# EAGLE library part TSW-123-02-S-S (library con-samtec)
THROUGH-HOLE .025" SQ POST HEADER Source: Samtec TSW.pdf
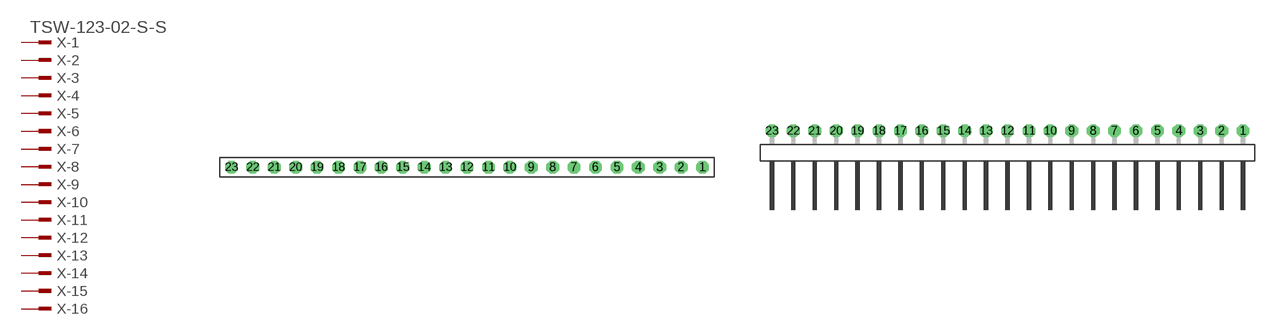
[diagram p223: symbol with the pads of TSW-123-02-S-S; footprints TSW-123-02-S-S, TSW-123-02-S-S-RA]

Designator prefix X; gates -1=MPINV -2=MPIN -3=MPIN -4=MPIN -5=MPIN -6=MPIN -7=MPIN -8=MPIN -9=MPIN -10=MPIN -11=MPIN -12=MPIN -13=MPIN -14=MPIN -15=MPIN -16=MPIN -17=MPIN -18=MPIN -19=MPIN -20=MPIN -21=MPIN -22=MPIN -23=MPIN

## TSW-123-02-S-S (OC_FARNELL: unknown; OC_NEWARK: unknown)  [TSW-123-02-S-S]
1  -1:1  pas
2  -2:1  pas
3  -3:1  pas
4  -4:1  pas
5  -5:1  pas
6  -6:1  pas
7  -7:1  pas
8  -8:1  pas
9  -9:1  pas
10  -10:1  pas
11  -11:1  pas
12  -12:1  pas
13  -13:1  pas
14  -14:1  pas
15  -15:1  pas
16  -16:1  pas
17  -17:1  pas
18  -18:1  pas
19  -19:1  pas
20  -20:1  pas
21  -21:1  pas
22  -22:1  pas
23  -23:1  pas

## TSW-123-02-S-S-RA (OC_FARNELL: unknown; OC_NEWARK: unknown)  [TSW-123-02-S-S-RA]
Pads as for TSW-123-02-S-S

## Footprint TSW-123-02-S-S (pad centres in mm)
THROUGH-HOLE .025" SQ POST HEADER Source: Samtec TSW.pdf
drill 1 pad 1.5 octagon: 1 27.94,0; 2 25.4,0; 3 22.86,0; 4 20.32,0; 5 17.78,0; 6 15.24,0; 7 12.7,0; 8 10.16,0; 9 7.62,0; 10 5.08,0; 11 2.54,0; 12 0,0; 13 -2.54,0; 14 -5.08,0; 15 -7.62,0; 16 -10.16,0; 17 -12.7,0; 18 -15.24,0; 19 -17.78,0; 20 -20.32,0; 21 -22.86,0; 22 -25.4,0; 23 -27.94,0

## Footprint TSW-123-02-S-S-RA (pad centres in mm)
THROUGH-HOLE .025" SQ POST HEADER Source: Samtec TSW.pdf
drill 1 pad 1.5 octagon: 1 27.94,1.524; 2 25.4,1.524; 3 22.86,1.524; 4 20.32,1.524; 5 17.78,1.524; 6 15.24,1.524; 7 12.7,1.524; 8 10.16,1.524; 9 7.62,1.524; 10 5.08,1.524; 11 2.54,1.524; 12 0,1.524; 13 -2.54,1.524; 14 -5.08,1.524; 15 -7.62,1.524; 16 -10.16,1.524; 17 -12.7,1.524; 18 -15.24,1.524; 19 -17.78,1.524; 20 -20.32,1.524; 21 -22.86,1.524; 22 -25.4,1.524; 23 -27.94,1.524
